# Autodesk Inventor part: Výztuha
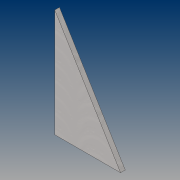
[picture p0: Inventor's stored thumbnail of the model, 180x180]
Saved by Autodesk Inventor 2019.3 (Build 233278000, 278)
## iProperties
Created: 2019-03
Part Number: Výztuha
Material: Ocel, měkká, svařovaná
Document SubType Name: Modeling
Designer: B-hon
Density: 7.85 g/cm^3
Appearance: Svar – měkká ocel
Author: B-hon
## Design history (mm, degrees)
sketch "Náčrt1"
  geometry: L1 (0, 0)-(0, 115); L2 (0, 0)-(70, 0); L3 (70, 0)-(0, 115)
  constraints: 6 end point, 1 horizontal, 1 vertical
  dimensions: "d0" = 115 distance of L1.start L1.end; "d1" = 70 distance of L1.start L2.end
extrude "Vysunutí1" new body sketch "Náčrt1" distance "d2" = 5; taper "d3" = 0 deg
node "Těleso1"
